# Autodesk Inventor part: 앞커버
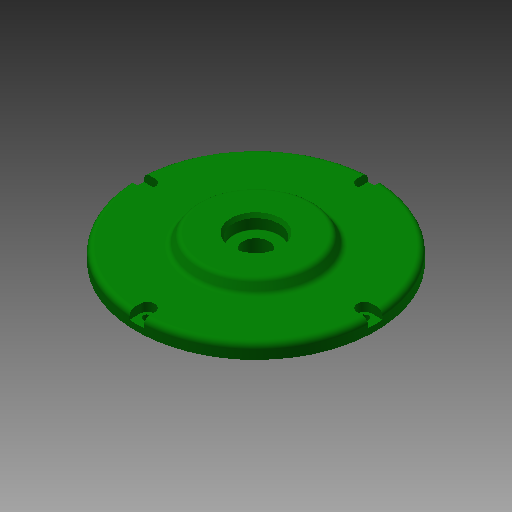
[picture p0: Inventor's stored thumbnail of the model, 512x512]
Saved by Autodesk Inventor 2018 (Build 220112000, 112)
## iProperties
Created: 2016-11
Part Number: 앞커버
Material: 일반
Document SubType Name: Modeling
Designer: mduedu
Density: 1 g/cm^3
Mass: 145.694 g
Surface Area: 366.671 cm^2
Volume: 145.694 cm^3
Appearance: 진녹색
Author: mduedu
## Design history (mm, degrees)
sketch "스케치1"
  geometry: L1 (22, -12.5)-(22, -30); L2 (22, -30)-(16, -33.464); L3 (16, -33.464)-(16, -65); L4 (16, -65)-(8, -65); L5 (8, -65)-(8, -53); L6 (8, -53)-(0, -53); L7 (0, -53)-(0, -14); L8 (0, 0)-(22, 0); L9 (8, -14)-(8, -7); L10 (8, -7)-(14.5, -7); L11 (14.5, -7)-(14.5, -12.5); L12 (0, -14)-(8, -14); L13 (14.5, -12.5)-(22, -12.5)
  constraints: 26 end point, 8 parallel, 3 perpendicular, 2 horizontal, 2 vertical alignment, 1 collinear
  dimensions: "d0" = 8 distance of L5.end L6.end; "d2" = 8 distance of L3.end L4.end; "d3" = 6 distance between parallel lines of L1 L3; "d4" = 120 deg angle of L3 L2; "d5" = 7.5 distance of L11.end L1.start; "d6" = 60 diameter of L1.end L8; "d7" = 14 diameter of L10 L8; "d8" = 28 diameter of L12 L8; "d9" = 25 diameter of L13 L8; "d10" = 106 diameter of L6 L8; "d11" = 130 diameter of L4 L8
revolve "회전1" sketch "스케치1" stored, may be unused: angle "d12" = 90 deg
fillet "모깎기1" dims "d13" = 0.3
fillet "모깎기2" dims "d14" = 3
chamfer "모따기1" distance "d15" = 1; stored, may be unused: second distance "d16" = 2, angle "d17" = 45 deg
fillet "모깎기3" dims "d18" = 0.3
chamfer "모따기2" distance "d36" = 2; stored, may be unused: second distance "d37" = 2, angle "d38" = 30 deg
sketch "스케치3"
  geometry: C1 r 65 at (0, 0) reference; A1 r 59 centre (0, 0) between (0, 59) and (59, 0); 2 further points
  constraints: 4 point on circle, 2 horizontal alignment, 2 vertical alignment, 1 centre point, 1 coincident
  dimensions: "d33" = 118 diameter of A1
sketch "스케치4"
  geometry: 4 further points
  constraints: 4 other
hole "구멍2" sketch "스케치4" at (0, 59), (-59, 0), (59, 0), (0, -59) diameter "d39" = 4.5; stored, may be unused: countersink angle "d43" = 90 deg, drill point angle "d45" = 0 deg; dims "d40" = 6, "d41" = 8, "d42" = 4.6, "d44" = 8
sketch "스케치6"
  geometry: L1 (-4, 5.877)-(-4, 0); L2 (4, 5.877)-(4, 0); A1 r 4 centre (0, 0) between (-2.712, 2.941) and (2.712, 2.941) reference; A2 r 65 centre (0, -59) between (-4, 5.877) and (4, 5.877) reference; 1 further point
  constraints: 4 end point, 4 point on circle, 2 tangent, 2 vertical
extrude "돌출2" cut sketch "스케치6" stored distance "d51" = 10; taper "d52" = 0 deg
sketch "스케치5"
  geometry: C1 r 22 at (0, 0); C2 r 45 at (0, 0); 1 further point
  constraints: 2 centre point, 2 coincident
  dimensions: "d46" = 44 diameter of C1; "d47" = 90 diameter of C2
extrude "돌출1" cut sketch "스케치5" distance "d48" = 8; taper "d49" = 0 deg
fillet "모깎기4" dims "d50" = 3
node "솔리드1"
pattern_circular "원형 패턴1" dims angle "d54" = 360 deg
